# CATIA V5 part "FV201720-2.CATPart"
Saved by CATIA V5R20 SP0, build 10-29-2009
Part number: FV201720-2
Revision: ANY
Definition: UNKNOWN
Nomenclature: FV201720-2
Source: Unknown
Bounding box of the stored display mesh (mm): x -8.5 to 8.5, y -15.5 to 0, z -8.5 to 8.5
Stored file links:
  C:\Users\Utente\Desktop\IO LAVORO\3D X SITO CF\CUMSA\3D files FV\FV 201720\FV201720-2.CATPart
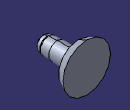
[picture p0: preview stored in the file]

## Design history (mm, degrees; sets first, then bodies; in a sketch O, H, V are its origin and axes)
Body1 "Chaflán1" (main body)
  Solid1: solid without history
